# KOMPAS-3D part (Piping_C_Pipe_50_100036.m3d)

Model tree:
1. Plane XY
2. Plane ZX
3. Plane ZY
4. X Axis
5. Y Axis
6. Z Axis
7. Origin
8. Path  (labels: Отвод 90 Dy 50; Труба Dy 50)
9. Plane of section
10. Section of pipe
11. Pipe
     Толщина стенки 1 = 1

Referenced files in C:\Program Files\ASCON\KOMPAS-3D V10\Libs\Piping\Models\Tanks\: Tanks.a3d
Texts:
  Pipe Dn 50
  Steel ASTM A295
  Three Point Plane
  Plane at Angle
  Line and Point Plane
  Axis through Two Vertices
  Axis of Feature
  Axis of Conical Surface
  Axis through Edge
  Приклеить элемент выдавливания
  Приклеить элемент вращения
  Приклеить кинематический элемент
  Приклеить элемент по сечениям
  Trim by Surface
  Trim by Sketch
  Feature with No History
  Intersection Axis of Two Planes
  Two Line Plane
  Line and Face Plane
  Bend by line
  Hole in sheet body
  Cut in sheet body
  Point in CM
  Linear Dimension from Line to Point
  Surface Finish Symbol
  Geometric Tolerance Symbol
  Текст на чертеже
  Линия-выноска #1
  Линия-выноска #2
  Линия-выноска #3
  Отклонения формы и база
  Марка координационной оси
  Марка/позиционное обозначение с линией-выноской
  Марка/позиционное обозначение на линии
  Марка/позиционное обозначение без линии-выноски
  Отвод 90 Dy 50
  Труба Dy 50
